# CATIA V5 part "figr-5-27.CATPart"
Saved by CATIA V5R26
Part number: Part1
Bounding box of the stored display mesh (mm): x -34.542 to 34.542, y -63.781 to 63.781, z 0 to 53
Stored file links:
  D:\_Deepak\CATIA\CATIA V5-6R2016_Deepak\Resources\Part files\Partfiles\c05_catia_v5_6r2016_prt\figr-5-27.CATPart
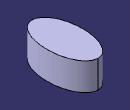
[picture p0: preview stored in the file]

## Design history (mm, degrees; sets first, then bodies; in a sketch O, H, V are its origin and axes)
Body1 (main body)
  Sketch1 on xy-plane, origin (0, 0, 0), H (1, 0, 0), V (0, 1, 0)
    line L1 (-75, 100) -> (75, 100)
    line L2 (75, 100) -> (75, -100)
    line L3 (75, -100) -> (-75, -100)
    line L4 (-75, -100) -> (-75, 100)
    axis line L5 (75, -100) -> (-75, 100)
    length L3 = 150
    length L2 = 200
    horizontal: L1 H, L3 H
    vertical: L2 V, L4 V
    midpoint: L5 O
  Pad1: profile Sketch1, direction (0, 0, 1), length 53
  Sketch2 on face of Pad1, origin (0, 0, 53), H (1, 0, 0), V (0, 1, 0)
    ellipse A1 centre (0, 0) semi-axes 63.781, 34.5424 rotation 270
    point P1 (0, -63.781)
    point P2 (34.5424, 0)
    coincidence: P1 V, P2 H, A1 P1, A1 P2
  Pocket1: profile Sketch2, direction (0, 0, -1), through (limit type 3), outer side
